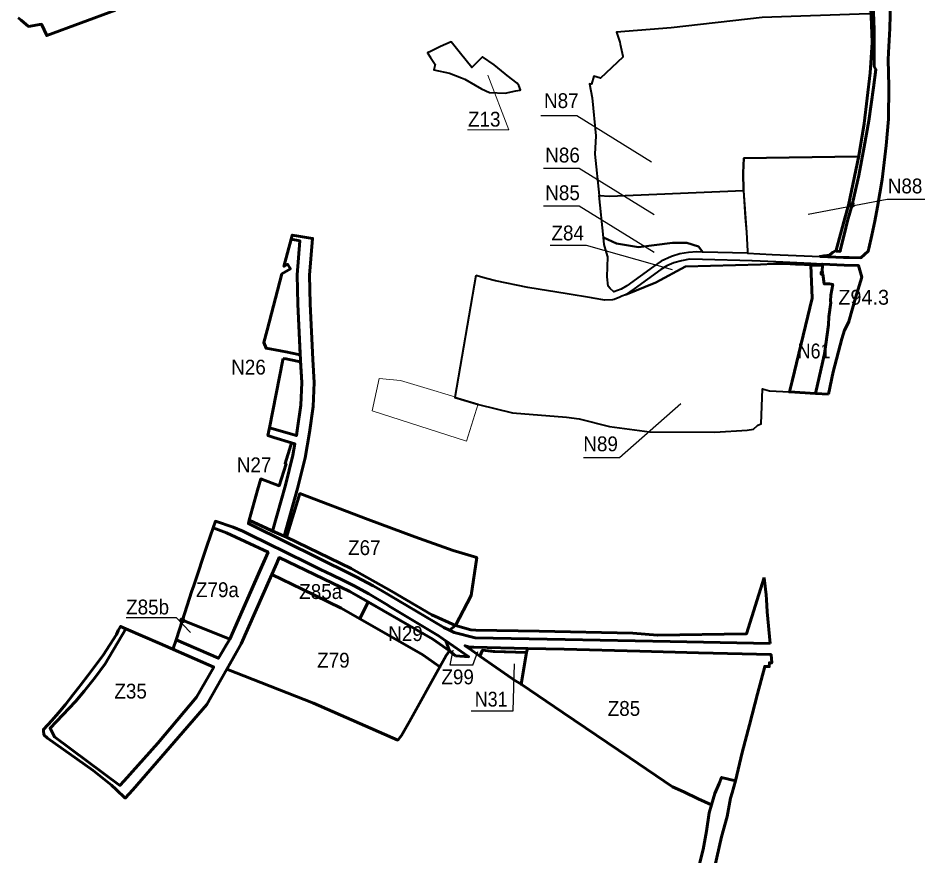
# Model space of a CAD drawing. Extents: x -650277 to -643425, y -1073980 to -1066720.
# Drawn here: x -646383 to -644916, y -1071727 to -1070373 of the extents above; entities that cross this region are included whole.
import ezdxf

# ---------------------------------------------------------------- set-up
doc = ezdxf.new("R2010")
doc.units = 0
doc.header["$LTSCALE"] = 9.6
doc.header["$PDMODE"] = 32
doc.header["$PDSIZE"] = 4.8
for name, color, linetype, lineweight in [('11', 7, 'Continuous', 60), ('15', 7, 'Continuous', 60), ('18', 7, 'Continuous', 60), ('2', 7, 'Continuous', 40), ('20', 7, 'Continuous', 60), ('40', 7, 'Continuous', 60), ('45', 7, 'Continuous', 60), ('59', 7, 'Continuous', 25), ('60', 7, 'Continuous', 60), ('63', 7, 'Continuous', 25), ('9', 7, 'Continuous', 60)]:
    doc.layers.add(name, color=color, linetype=linetype, lineweight=lineweight)

msp = doc.modelspace()

# ---------------------------------------------------------------- linework, layer by layer
at = {"layer": '11'}
msp.add_lwpolyline([(-646066.165, -1071422.155), (-646153.5, -1071383.85), (-646208.577, -1071360.044), (-646241.68, -1071416.887), (-646258.487, -1071439.265), (-646275.615, -1071460.886), (-646289.976, -1071477.514), (-646330.914, -1071521.11), (-646324, -1071535), (-646217.978, -1071613.552), (-646211.407, -1071606.247), (-646156.471, -1071545.166), (-646094.063, -1071471.007)], close=True, dxfattribs=at)
at = {"layer": '15'}
for points in [[(-645004.523, -1070326.697), (-645004.434, -1070327.302), (-645001.312, -1070412.099), (-645004.327, -1070461.264), (-645014.277, -1070543.11), (-645023.048, -1070595.033), (-645039.574, -1070675.065)], [(-645033.53, -1070674.55), (-645022.64, -1070626.93), (-645014.07, -1070580.72), (-645006.44, -1070538.78), (-644998.92, -1070484.58), (-644995.14, -1070455.72), (-644998.17, -1070450.59), (-644998.25, -1070430.5), (-644997.87, -1070391.16), (-644999.47, -1070349.63)], [(-645039.574, -1070675.065), (-645045.493, -1070696.321), (-645059.308, -1070747.712), (-645059.403, -1070749.195), (-645053.21, -1070749.75), (-645052.4, -1070746.427), (-645046.63, -1070722.77), (-645041, -1070700.44), (-645033.53, -1070674.55)], [(-645955.342, -1071233.725), (-645973.324, -1071224.925), (-645989.7, -1071216.91), (-645997.62, -1071213.03), (-646019.41, -1071202.36), (-646035.06, -1071195.87), (-646063.59, -1071186.33), (-646067.097, -1071196.699), (-646045.462, -1071204.917), (-646015.387, -1071218.854), (-645978.403, -1071236.481), (-646040.084, -1071376.813), (-646058.719, -1071407.796), (-646127.301, -1071378.036), (-646131.79, -1071391.83), (-646132.229, -1071393.179), (-646066.165, -1071422.155), (-646094.063, -1071471.007), (-646156.471, -1071545.166), (-646211.407, -1071606.247), (-646217.978, -1071613.552)], [(-645701.44, -1071372.25), (-645782.32, -1071323.5), (-645784.92, -1071321.93), (-645815.65, -1071303.41), (-645839.37, -1071290.6), (-645854.1, -1071282.93), (-645856.26, -1071281.91), (-645875.48, -1071272.81), (-645893.41, -1071264.04), (-645907.62, -1071257.08), (-645955.342, -1071233.725)], [(-646223.928, -1071620.168), (-646209.322, -1071634.004), (-646197.398, -1071620.579), (-646077.593, -1071482.499), (-646021.674, -1071384.575), (-645964.396, -1071254.314), (-645960.34, -1071245.09)], [(-645960.34, -1071245.09), (-645846, -1071300), (-645712, -1071377)], [(-646217.978, -1071613.552), (-646324, -1071535), (-646330.914, -1071521.11), (-646289.976, -1071477.514), (-646275.615, -1071460.886), (-646275.615, -1071460.886), (-646258.487, -1071439.265), (-646241.68, -1071416.887), (-646208.577, -1071360.044), (-646217.049, -1071356.382), (-646220.61, -1071363.16), (-646223.77, -1071369.24), (-646245.1, -1071403.04), (-646269.2, -1071435.22), (-646281.99, -1071451.4), (-646283.52, -1071453.34), (-646293.87, -1071466.43), (-646306.14, -1071482.86), (-646317.52, -1071496.12), (-646327.97, -1071508.29), (-646341.88, -1071522.81), (-646341.66, -1071524.87), (-646340.93, -1071531.64), (-646335.3, -1071537.05), (-646261.46, -1071589.38), (-646231.43, -1071613.06), (-646223.928, -1071620.168)], [(-645712, -1071377), (-645685.098, -1071395.824), (-645690.677, -1071379.721)]]:
    msp.add_lwpolyline(points, dxfattribs=at)
for points in [[(-645911.345, -1070788.463), (-645906.373, -1070728.716), (-645929.077, -1070725.068), (-645939.27, -1070723.43), (-645940.955, -1070729.799), (-645926.784, -1070732.812), (-645931.369, -1070787.913), (-645930.036, -1070835.367), (-645926.084, -1070925.481), (-645923.919, -1070961.855), (-645925.626, -1070998.754), (-645931.24, -1071039.686), (-645932.635, -1071047.688), (-645976.17, -1071035.39), (-645978.58, -1071047.68), (-645973.77, -1071049.17), (-645968.97, -1071050.66), (-645940.25, -1071059.59), (-645934.978, -1071061.119), (-645938.15, -1071079.311), (-645950.283, -1071128.057), (-645970.966, -1071202.169), (-645952.419, -1071210.117), (-645930.943, -1071133.161), (-645918.57, -1071083.449), (-645911.474, -1071042.764), (-645905.69, -1071000.578), (-645903.891, -1070961.723), (-645906.11, -1070924.449), (-645910.048, -1070834.649)], [(-645694.15, -1071357.83), (-645684.785, -1071362.539), (-645674.947, -1071355.071), (-645713.428, -1071337.765), (-645778.69, -1071299.362), (-645844.079, -1071262.487), (-645948.761, -1071211.885), (-645967, -1071204), (-646008.714, -1071184.746), (-646010.14, -1071190.08), (-646004.65, -1071192.55), (-645951.118, -1071219.11), (-645843.45, -1071272.53), (-645835.76, -1071276.35), (-645808.13, -1071290.78), (-645795.97, -1071297.93), (-645694.15, -1071357.83)]]:
    msp.add_lwpolyline(points, close=True, dxfattribs=at)
msp.add_arc((-645538.107, -1071148.434), 277.076, 233.87926, 236.5888, dxfattribs=at)
msp.add_point((-645033.53, -1070674.55), dxfattribs=at)
at = {"layer": '18'}
for points in [[(-645678.86, -1071233.58), (-645741.09, -1071211.36), (-645816.47, -1071183.63), (-645926.81, -1071141.595), (-645948.761, -1071211.885)], [(-645948.761, -1071211.885), (-645844.079, -1071262.487), (-645778.69, -1071299.362), (-645713.428, -1071337.765), (-645674.947, -1071355.071)], [(-645674.947, -1071355.071), (-645650.09, -1071306.433), (-645640.737, -1071244.963), (-645678.86, -1071233.58)]]:
    msp.add_lwpolyline(points, dxfattribs=at)
at = {"layer": '2'}
for points in [[(-645023.048, -1070595.033), (-645014.277, -1070543.11), (-645004.327, -1070461.264), (-645001.312, -1070412.099), (-645003.03, -1070365.427), (-645003.102, -1070365.432), (-645006.86, -1070365.38), (-645179.26, -1070371.74), (-645326.62, -1070388.32), (-645414.65, -1070395.37), (-645409.38, -1070411.41), (-645408.66, -1070414.62), (-645404.34, -1070433.93), (-645404.4, -1070435.88), (-645440.61, -1070469.53), (-645451.226, -1070466.394), (-645455.09, -1070479.21), (-645458.46, -1070478.86), (-645454.02, -1070501.52), (-645448.36, -1070563), (-645449.82, -1070592.72), (-645442.834, -1070659.455)], [(-645208.96, -1070599.22), (-645025.12, -1070596.42), (-645023.346, -1070596.478), (-645023.048, -1070595.033)], [(-645059.421, -1070749.039), (-645059.308, -1070747.712), (-645045.493, -1070696.321), (-645039.574, -1070675.065), (-645039.338, -1070673.923), (-645023.346, -1070596.478), (-645025.12, -1070596.42), (-645208.96, -1070599.22), (-645209.79, -1070622.69), (-645209.41, -1070651.2)], [(-645209.41, -1070651.2), (-645209.79, -1070622.69), (-645208.96, -1070599.22)], [(-645442.834, -1070659.455), (-645426.34, -1070660.33), (-645209.41, -1070651.2)], [(-645209.41, -1070651.2), (-645207.88, -1070674.2), (-645204.66, -1070718.51)], [(-645204.66, -1070718.51), (-645203.13, -1070749.36), (-645202.96, -1070752.89), (-645163.06, -1070754.64), (-645085.58, -1070758.04), (-645079.38, -1070756.91), (-645070.3, -1070755.92), (-645065.17, -1070751.39)], [(-645065.17, -1070751.39), (-645060.538, -1070749.039), (-645059.421, -1070749.039)], [(-645100.268, -1070771.946), (-645143, -1070770), (-645161, -1070770), (-645182, -1070771), (-645303, -1070774), (-645351, -1070800), (-645400.05, -1070819.84), (-645406.09, -1070822.34), (-645409.52, -1070823.76), (-645418.67, -1070827.72), (-645421.09, -1070827.89), (-645433.49, -1070828.76), (-645452.31, -1070825.52), (-645455.184, -1070825.042)], [(-645130.749, -1070959.561), (-645098.438, -1070825.558), (-645100.268, -1070771.946)], [(-645642.52, -1070788.7), (-645676.292, -1070985.89), (-645637.94, -1070997.4), (-645583.18, -1071010.7), (-645495.87, -1071017.81)], [(-645455.184, -1070825.042), (-645494.82, -1070818.45), (-645558.3, -1070808), (-645610.25, -1070797.55), (-645625, -1070793.5), (-645642.52, -1070788.7)], [(-645495.87, -1071017.81), (-645475.01, -1071020.72), (-645426.38, -1071032.8), (-645361.54, -1071041.54), (-645255.93, -1071042.36), (-645203.66, -1071038.81), (-645193.24, -1071037.31), (-645186.18, -1071030.83), (-645180.72, -1071028.86), (-645178.73, -1070972.35), (-645167.47, -1070975.2), (-645134.973, -1070977.077), (-645134.973, -1070977.077), (-645130.749, -1070959.561)]]:
    msp.add_lwpolyline(points, dxfattribs=at)
for points in [[(-645594.769, -1070494.065), (-645577.47, -1070490.3), (-645571.13, -1070488.89), (-645569.97, -1070488.3), (-645572.86, -1070481.41), (-645575.7, -1070477.77), (-645591.49, -1070465.19), (-645594.62, -1070462.7), (-645612.77, -1070447.82), (-645631.63, -1070435.3), (-645636.42, -1070439.93), (-645648.9, -1070452.38), (-645666.99, -1070429.58), (-645682.02, -1070410.65), (-645699.33, -1070418.25), (-645714.74, -1070425.84), (-645720.48, -1070428.75), (-645715.56, -1070436.27), (-645708.28, -1070447.28), (-645710.14, -1070456.31), (-645684.78, -1070461.52), (-645665.6, -1070469.04), (-645660.29, -1070471.12), (-645643.4, -1070481.02), (-645633.35, -1070486.91), (-645620.22, -1070493)], [(-645208.96, -1070599.22), (-645209.79, -1070622.69), (-645209.41, -1070651.2), (-645207.88, -1070674.2), (-645204.66, -1070718.51), (-645203.13, -1070749.36), (-645202.96, -1070752.89), (-645163.06, -1070754.64), (-645085.58, -1070758.04), (-645079.38, -1070756.91), (-645070.3, -1070755.92), (-645065.17, -1070751.39), (-645060.46, -1070749.1), (-645059.421, -1070749.039), (-645059.308, -1070747.712), (-645045.493, -1070696.321), (-645039.574, -1070675.065), (-645028.384, -1070620.876), (-645023.346, -1070596.478), (-645025.12, -1070596.42)], [(-645442.836, -1070659.455), (-645426.34, -1070660.33), (-645209.41, -1070651.2), (-645206.7, -1070694.76), (-645204.66, -1070718.51), (-645203.13, -1070749.36), (-645202.96, -1070752.89), (-645275.236, -1070750.954), (-645282, -1070742), (-645301, -1070736), (-645324, -1070736), (-645379, -1070743), (-645415, -1070737), (-645435.711, -1070727.497)], [(-645275.236, -1070750.954), (-645285.11, -1070750.69), (-645298.41, -1070751.48), (-645312.2, -1070753.77), (-645325.82, -1070757.94), (-645342.41, -1070765.76), (-645354.98, -1070774.28), (-645398.04, -1070805.44), (-645407.37, -1070810.95), (-645419.18, -1070815.44), (-645424.969, -1070809.563), (-645428.39, -1070806.09), (-645430, -1070790.68), (-645428.73, -1070758.67), (-645430.84, -1070751.43), (-645434.53, -1070738.77), (-645435.711, -1070727.497), (-645415, -1070737), (-645379, -1070743), (-645324, -1070736), (-645301, -1070736), (-645282, -1070742)], [(-645303, -1070774), (-645182, -1070771), (-645161, -1070770), (-645143, -1070770), (-645125.217, -1070770.81), (-645081.75, -1070772.79), (-645081.6, -1070770.362), (-645100.32, -1070769.5), (-645156.988, -1070766.884), (-645195.527, -1070765.319), (-645195.527, -1070765.319), (-645275.8, -1070762.66), (-645296.51, -1070762.52), (-645309.78, -1070764.88), (-645321.9, -1070768.47), (-645333.12, -1070773.33), (-645342.94, -1070779.31), (-645385.99, -1070810.35), (-645400.05, -1070819.84), (-645351, -1070800)], [(-645303, -1070774), (-645182, -1070771), (-645161, -1070770), (-645143, -1070770), (-645125.217, -1070770.81), (-645081.75, -1070772.79), (-645081.6, -1070770.362), (-645100.32, -1070769.5), (-645156.988, -1070766.884), (-645195.527, -1070765.319), (-645195.527, -1070765.319), (-645275.8, -1070762.66), (-645296.51, -1070762.52), (-645309.78, -1070764.88), (-645321.9, -1070768.47), (-645333.12, -1070773.33), (-645342.94, -1070779.31), (-645385.99, -1070810.35), (-645400.05, -1070819.84), (-645351, -1070800)]]:
    msp.add_lwpolyline(points, close=True, dxfattribs=at)
at = {"layer": '2', "lineweight": 13}
msp.add_lwpolyline([(-645638.648, -1070996.51), (-645657.288, -1071056.48), (-645809.828, -1071007.55), (-645798.468, -1070955.63), (-645764.238, -1070958.82)], close=True, dxfattribs=at)
at = {"layer": '20'}
for points in [[(-645990.48, -1071263.958), (-645978.403, -1071236.481), (-646015.387, -1071218.854), (-646045.462, -1071204.917), (-646067.097, -1071196.699), (-646076.713, -1071225.138)], [(-646076.713, -1071225.138), (-646098.66, -1071290.03), (-646102.011, -1071300.326), (-646117.031, -1071346.48)], [(-646117.031, -1071346.48), (-646040.084, -1071376.813), (-645990.48, -1071263.958)]]:
    msp.add_lwpolyline(points, dxfattribs=at)
msp.add_lwpolyline([(-645972.423, -1071272.568), (-646021.674, -1071384.575), (-646039.658, -1071416.067), (-646044.948, -1071425.333), (-645905.027, -1071480.359), (-645768.62, -1071540.17), (-645762.54, -1071533.015), (-645749.631, -1071509.908), (-645700.38, -1071421.746), (-645728.054, -1071402.382), (-645806.036, -1071357.564), (-645829.706, -1071343.963), (-645859.986, -1071326.563), (-645923.023, -1071296.291), (-645972.422, -1071272.568)], close=True, dxfattribs=at)
msp.add_point((-646117.031, -1071346.48), dxfattribs=at)
at = {"layer": '40'}
for points in [[(-645926.457, -1070916.969), (-645930.036, -1070835.367), (-645931.369, -1070787.913), (-645926.784, -1070732.812), (-645940.955, -1070729.799), (-645952.65, -1070773.98), (-645946.81, -1070770.47), (-645942.3, -1070777.96), (-645955.86, -1070786.21), (-645980.01, -1070877.28), (-645985.28, -1070897.13), (-645981.48, -1070906.35), (-645958.21, -1070910.84)], [(-645958.21, -1070910.84), (-645946.85, -1070913.03), (-645941.94, -1070913.98), (-645926.457, -1070916.969)], [(-645954.01, -1070922.8), (-645954.492, -1070925.251), (-645976.17, -1071035.39), (-645932.635, -1071047.688), (-645931.24, -1071039.686), (-645925.626, -1070998.754), (-645923.919, -1070961.855), (-645925.908, -1070928.435)], [(-645925.908, -1070928.435), (-645944.08, -1070924.79), (-645948.99, -1070923.81), (-645954.01, -1070922.8)]]:
    msp.add_lwpolyline(points, dxfattribs=at)
for points in [[(-645970.966, -1071202.169), (-645950.283, -1071128.057), (-645938.15, -1071079.311), (-645934.978, -1071061.119), (-645940.25, -1071059.59), (-645941.45, -1071063.3), (-645950.96, -1071092.8), (-645949.21, -1071093.62), (-645960.66, -1071128.71), (-645990.14, -1071117.76), (-645995.74, -1071136.22), (-646008.714, -1071184.746)], [(-645700.38, -1071421.746), (-645690.056, -1071403.266), (-645685.098, -1071395.824), (-645712, -1071377), (-645816.714, -1071316.828), (-645829.706, -1071343.963), (-645806.036, -1071357.564), (-645728.054, -1071402.382)], [(-645583.18, -1071441.3), (-645580.947, -1071442.658), (-645569.07, -1071449.88), (-645560.11, -1071398.7), (-645611.58, -1071397.14), (-645631.44, -1071394.9), (-645635.795, -1071404.403)]]:
    msp.add_lwpolyline(points, close=True, dxfattribs=at)
at = {"layer": '45'}
for points in [[(-645100.268, -1070771.946), (-645098.438, -1070825.558), (-645130.749, -1070959.561), (-645134.972, -1070977.077), (-645092.67, -1070979.52)], [(-645083.49, -1070786.92), (-645083.95, -1070783.89), (-645081.57, -1070783.53), (-645081.85, -1070781.59), (-645081.75, -1070772.79), (-645100.268, -1070771.946)], [(-645092.67, -1070979.52), (-645078.23, -1070915.65), (-645071.77, -1070868.73), (-645071.18, -1070855.63), (-645068.07, -1070832.72), (-645068.52, -1070830.52), (-645068.07, -1070820.37), (-645065.01, -1070803.22), (-645070.2, -1070802.33), (-645078.85, -1070802.46), (-645081.13, -1070786.56), (-645083.49, -1070786.92)]]:
    msp.add_lwpolyline(points, dxfattribs=at)
at = {"layer": '59', "lineweight": 13}
msp.add_lwpolyline([(-645656, -1070553), (-645589, -1070553), (-645623, -1070465)], dxfattribs=at)
at = {"layer": '59'}
for points in [[(-645537, -1070530), (-645479, -1070530), (-645358, -1070605)], [(-645533, -1070615), (-645475, -1070615), (-645354, -1070690)], [(-644916, -1070666), (-644977, -1070666), (-645105, -1070690)], [(-645533, -1070676), (-645475, -1070676), (-645354, -1070751)], [(-645522, -1070740), (-645464, -1070740), (-645325, -1070779)], [(-645468, -1071083), (-645410, -1071083), (-645311, -1070996)]]:
    msp.add_lwpolyline(points, dxfattribs=at)
at = {"layer": '60'}
for points in [[(-645033.53, -1070674.55), (-645041, -1070700.44), (-645046.63, -1070722.77), (-645052.4, -1070746.427), (-645053.21, -1070749.75), (-645060.46, -1070749.1), (-645065.17, -1070751.39), (-645070.3, -1070755.92), (-645079.38, -1070756.91), (-645085.58, -1070758.04), (-645047.39, -1070759.71), (-645038.44, -1070759.83), (-645019.57, -1070760.07), (-645007.68, -1070749.5), (-645006.739, -1070745.384), (-645001.71, -1070723.39), (-644997.14, -1070700.88), (-644992.6, -1070677.92), (-644985.04, -1070633.43), (-644978.44, -1070578.56), (-644975.05, -1070536.16), (-644974.44, -1070482.48), (-644975.29, -1070440.14), (-644974.69, -1070427.86), (-644972.48, -1070389.15), (-644971.37, -1070345.98)], [(-644999.47, -1070349.63), (-644997.87, -1070391.16), (-644998.25, -1070430.5), (-644998.17, -1070450.59), (-644995.14, -1070455.72), (-644998.92, -1070484.58), (-645006.44, -1070538.78), (-645014.07, -1070580.72), (-645022.64, -1070626.93), (-645033.53, -1070674.55)], [(-645071.99, -1070980.72), (-645064.39, -1070944.7), (-645050.47, -1070891.48), (-645045.74, -1070877.19), (-645043, -1070871.35), (-645039.25, -1070863.33), (-645028.25, -1070824.83), (-645018.18, -1070791.34), (-645023.25, -1070772.62), (-645046.46, -1070771.98), (-645081.6, -1070770.362), (-645081.75, -1070772.79), (-645081.85, -1070781.59), (-645081.57, -1070783.53)], [(-645081.57, -1070783.53), (-645083.95, -1070783.89), (-645083.49, -1070786.92), (-645081.13, -1070786.56), (-645078.85, -1070802.46), (-645070.2, -1070802.33)], [(-645070.2, -1070802.33), (-645065.01, -1070803.22), (-645068.07, -1070820.37)], [(-645068.07, -1070820.37), (-645068.52, -1070830.52), (-645068.07, -1070832.72), (-645071.18, -1070855.63), (-645071.77, -1070868.73), (-645078.23, -1070915.65)], [(-645078.23, -1070915.65), (-645092.67, -1070979.52), (-645071.99, -1070980.72)], [(-645176.14, -1071277.26), (-645204.341, -1071368.19), (-645348.55, -1071370.559), (-645388.619, -1071366.991), (-645539.738, -1071364.092), (-645642.431, -1071362.259), (-645650.28, -1071362.07), (-645674.947, -1071355.071), (-645684.785, -1071362.539), (-645677.58, -1071366.16), (-645643.56, -1071374.75), (-645497.84, -1071377.53), (-645327.76, -1071380.76), (-645166.34, -1071384.07)], [(-645166.34, -1071384.07), (-645170.91, -1071332.86), (-645172.03, -1071312.96), (-645172.85, -1071305.45), (-645175.4, -1071281.93), (-645175.67, -1071279.45), (-645176.14, -1071277.26)], [(-645339.904, -1072462.677), (-645347.551, -1072443.527), (-645347.677, -1072391.355), (-645346.62, -1072330.914), (-645343.458, -1072278.998), (-645339.908, -1072235.158), (-645335.367, -1072185.207), (-645325.498, -1072102.789), (-645309.01, -1071998.147), (-645285.617, -1071875.733), (-645244.798, -1071696.585), (-645235.793, -1071663.703), (-645230.436, -1071634.261), (-645227.905, -1071625.277), (-645222.48, -1071606.08)], [(-645222.48, -1071606.08), (-645244.81, -1071600.61), (-645248.786, -1071610.383), (-645255.662, -1071626.67)], [(-645255.662, -1071626.67), (-645261.094, -1071645.025), (-645264.841, -1071657.687), (-645269.077, -1071687.396), (-645274.868, -1071717.176), (-645286.175, -1071761.228), (-645300.076, -1071820.179), (-645313.153, -1071883.081)]]:
    msp.add_lwpolyline(points, dxfattribs=at)
for points in [[(-645816.714, -1071316.828), (-645846, -1071300), (-645960.34, -1071245.09), (-645964.396, -1071254.314), (-645972.422, -1071272.568), (-645972.422, -1071272.568), (-645923.023, -1071296.291), (-645859.986, -1071326.563), (-645829.705, -1071343.962)], [(-646045.393, -1071385.64), (-646040.084, -1071376.813), (-646117.031, -1071346.48), (-646127.301, -1071378.036), (-646058.719, -1071407.796)], [(-645675.177, -1071403.922), (-645675.177, -1071403.922), (-645653.742, -1071405.36), (-645690.677, -1071379.721), (-645685.098, -1071395.824)], [(-645614.201, -1071396.844), (-645560.11, -1071398.7), (-645558.872, -1071391.801), (-645558.9, -1071391.8), (-645645.368, -1071389.96), (-645651.93, -1071389.82), (-645659.6, -1071387.71), (-645647.727, -1071396.036), (-645635.795, -1071404.403), (-645631.44, -1071394.9)], [(-645560.11, -1071398.7), (-645569.07, -1071449.88), (-645501.37, -1071495.68), (-645393.34, -1071568.75), (-645324.17, -1071615.53), (-645324.17, -1071615.53), (-645305.78, -1071624.13), (-645282.54, -1071634.997), (-645261.094, -1071645.025), (-645255.662, -1071626.67), (-645248.786, -1071610.383), (-645244.81, -1071600.61), (-645222.48, -1071606.08), (-645222.48, -1071606.08), (-645211.27, -1071560.01), (-645199.61, -1071515.68), (-645186.67, -1071465.55), (-645175.06, -1071420.93), (-645167.58, -1071421.19), (-645167.37, -1071415.2), (-645163.56, -1071415.3), (-645164.76, -1071401.79), (-645281.92, -1071398.82), (-645376.87, -1071396.41), (-645499.65, -1071393.3), (-645558.9, -1071391.8), (-645645.368, -1071389.96), (-645651.93, -1071389.82), (-645659.6, -1071387.71), (-645647.727, -1071396.036), (-645635.795, -1071404.403), (-645631.44, -1071394.9), (-645614.201, -1071396.844)]]:
    msp.add_lwpolyline(points, close=True, dxfattribs=at)
msp.add_point((-645033.53, -1070674.55), dxfattribs=at)
at = {"layer": '63'}
msp.add_line((-645647, -1071419), (-645639, -1071397), dxfattribs=at)
for points in [[(-646208, -1071342), (-646127, -1071342), (-646104, -1071366)], [(-645647, -1071419), (-645684, -1071419), (-645679, -1071395)], [(-645650, -1071493), (-645582, -1071493), (-645580, -1071417)]]:
    msp.add_lwpolyline(points, dxfattribs=at)
at = {"layer": '9'}
msp.add_lwpolyline([(-646382.67, -1070371.94), (-646377.86, -1070375.71), (-646365.7, -1070385.89), (-646344.93, -1070382.33), (-646336.35, -1070400.9), (-646225.15, -1070359.46)], dxfattribs=at)

# ---------------------------------------------------------------- texts
at = {"layer": '59', "width": 0.95}
for s, p in [('N87', (-645532, -1070518)), ('Z13', (-645655, -1070548)), ('N86', (-645530, -1070606)), ('N88', (-644976, -1070656)), ('N85', (-645530, -1070667)), ('Z84', (-645520, -1070732)), ('N89', (-645468.436, -1071073.045))]:
    msp.add_text(s, height=24, dxfattribs=at).set_placement(p)
at = {"layer": '63'}
msp.add_text('Z94.3', height=24, dxfattribs=at).set_placement((-645056, -1070836))
for s, width, p in [('N61', 0.9, (-645121.693, -1070922.874)), ('N26', 0.95, (-646038, -1070949)), ('N27', 0.95, (-646029, -1071107)), ('Z67', 0.95, (-645849, -1071241)), ('Z79a', 0.95, (-646095, -1071309)), ('Z85a', 0.95, (-645928, -1071312)), ('Z85b', 0.95, (-646208, -1071337)), ('N29', 0.95, (-645784, -1071380)), ('Z79', 0.95, (-645899, -1071423)), ('Z99', 0.95, (-645698, -1071450)), ('Z35', 0.95, (-646227, -1071473)), ('N31', 0.9, (-645644, -1071486)), ('Z85', 0.95, (-645429, -1071501))]:
    msp.add_text(s, height=24, dxfattribs=dict(at, width=width)).set_placement(p)

doc.saveas('drawing.dxf')
